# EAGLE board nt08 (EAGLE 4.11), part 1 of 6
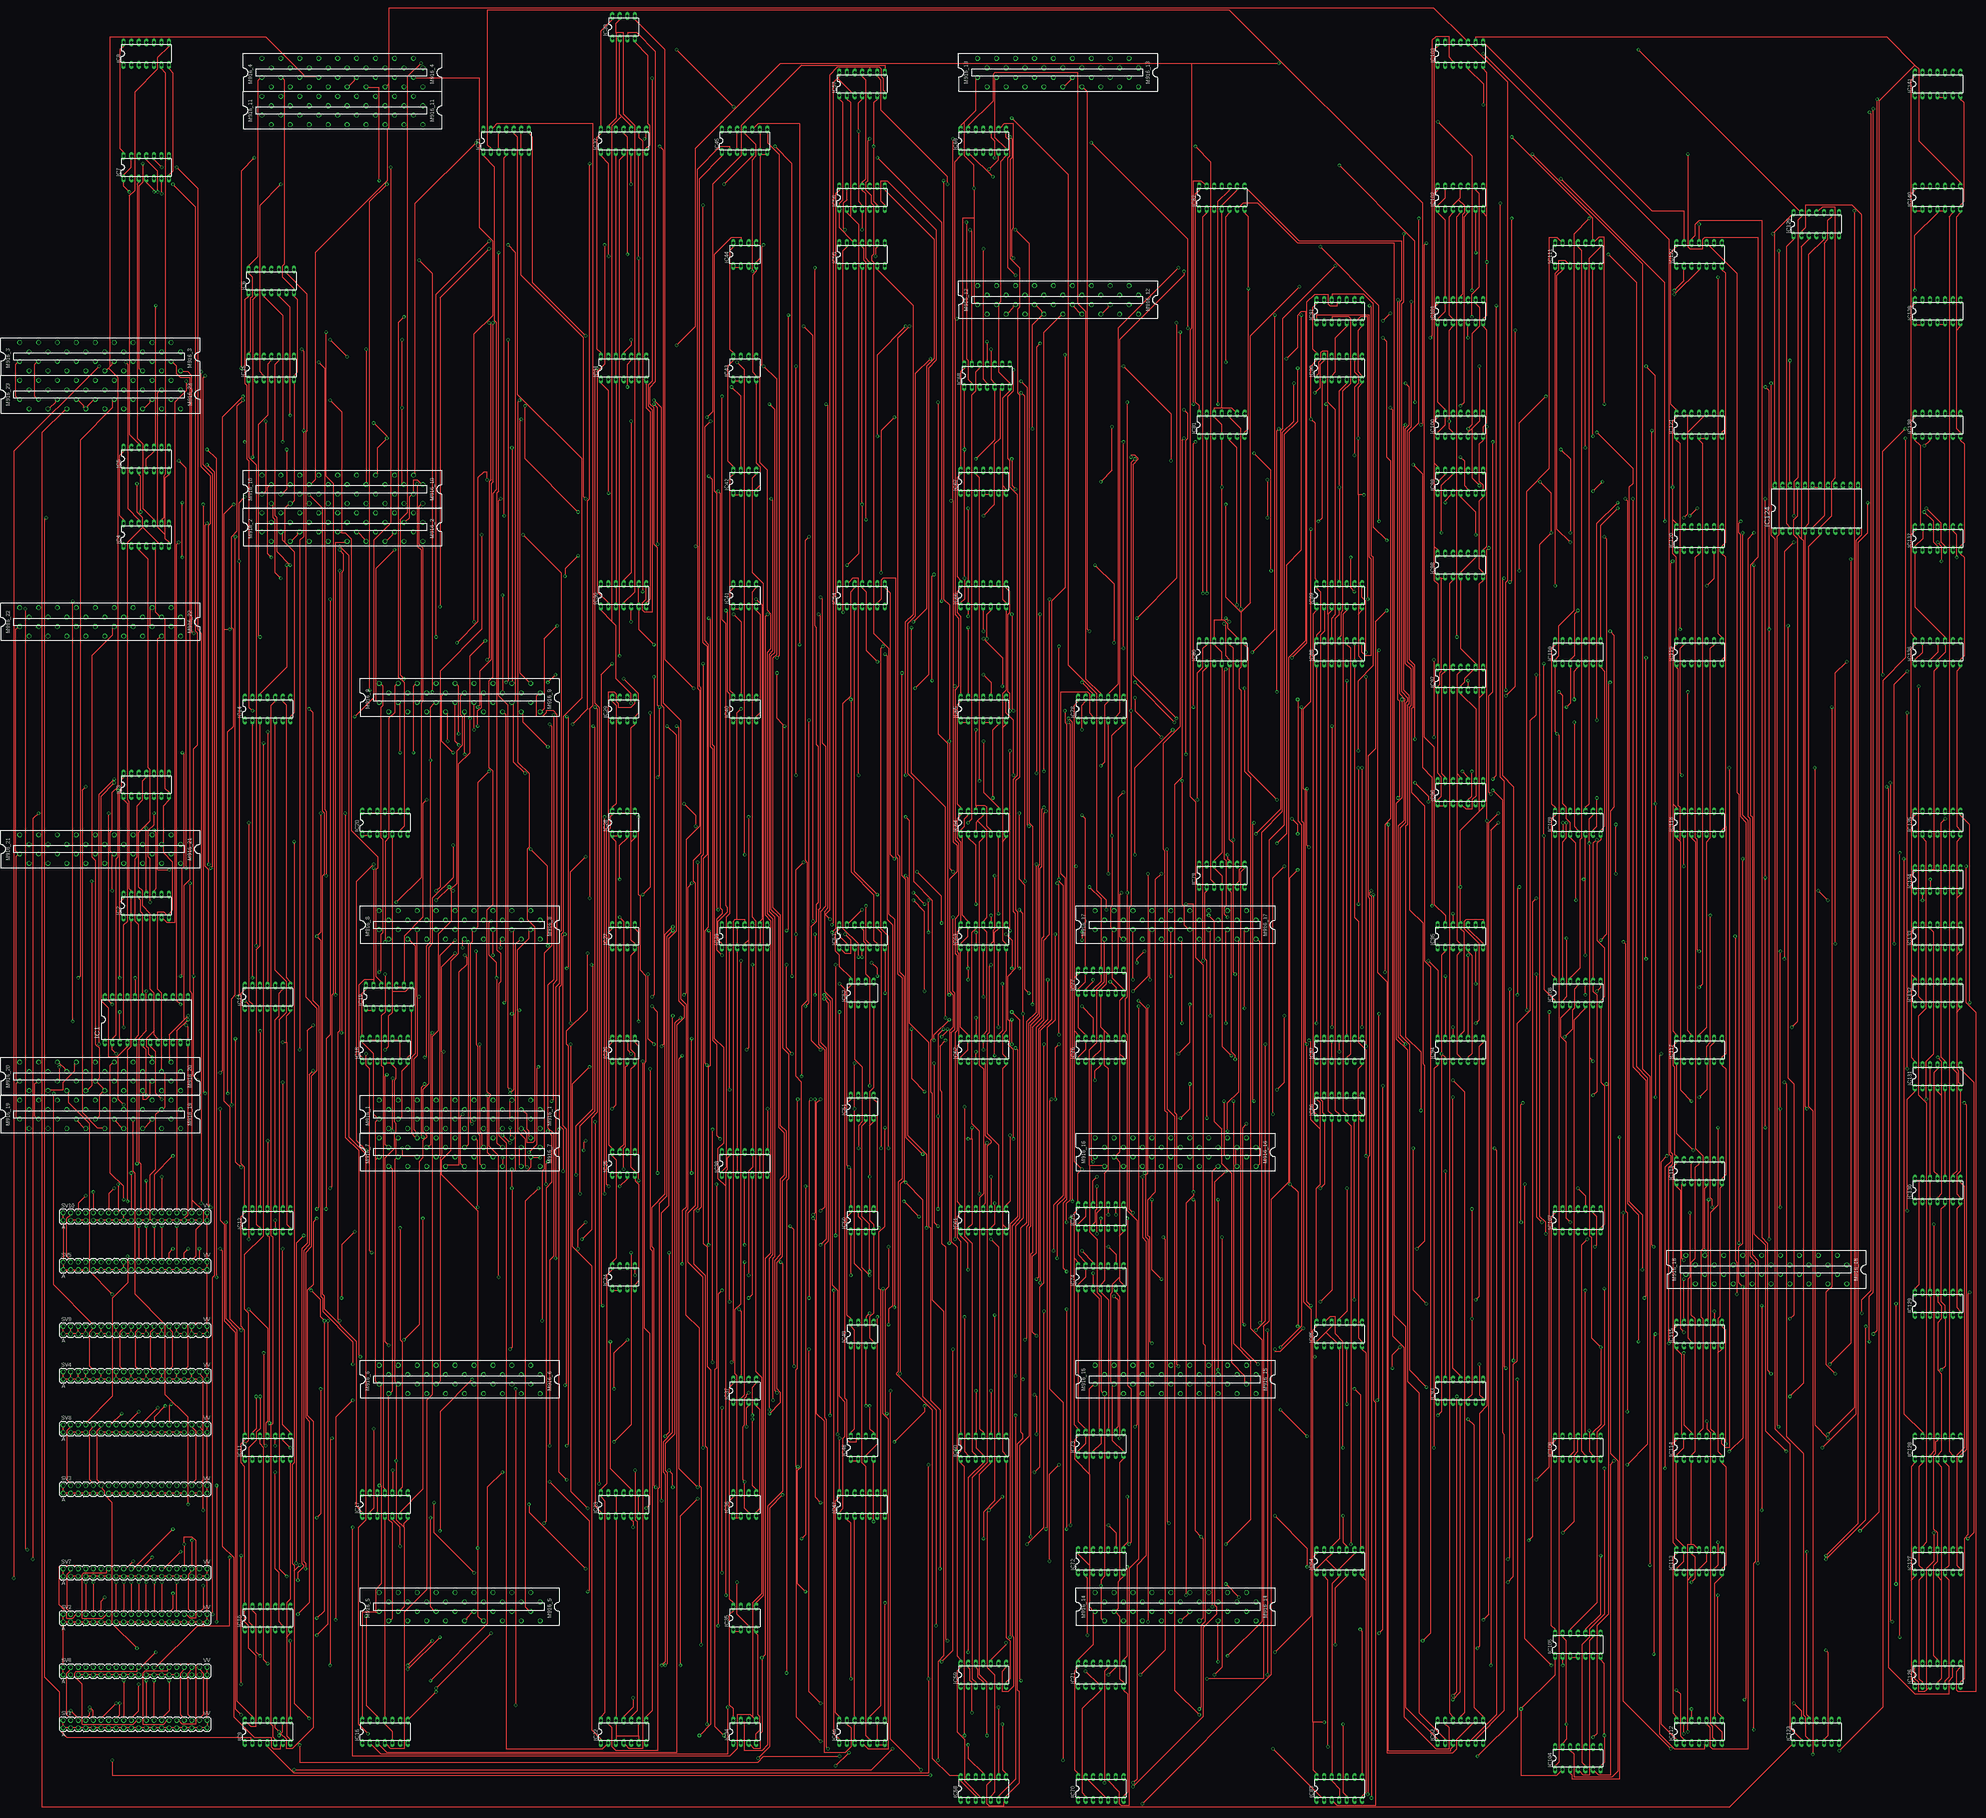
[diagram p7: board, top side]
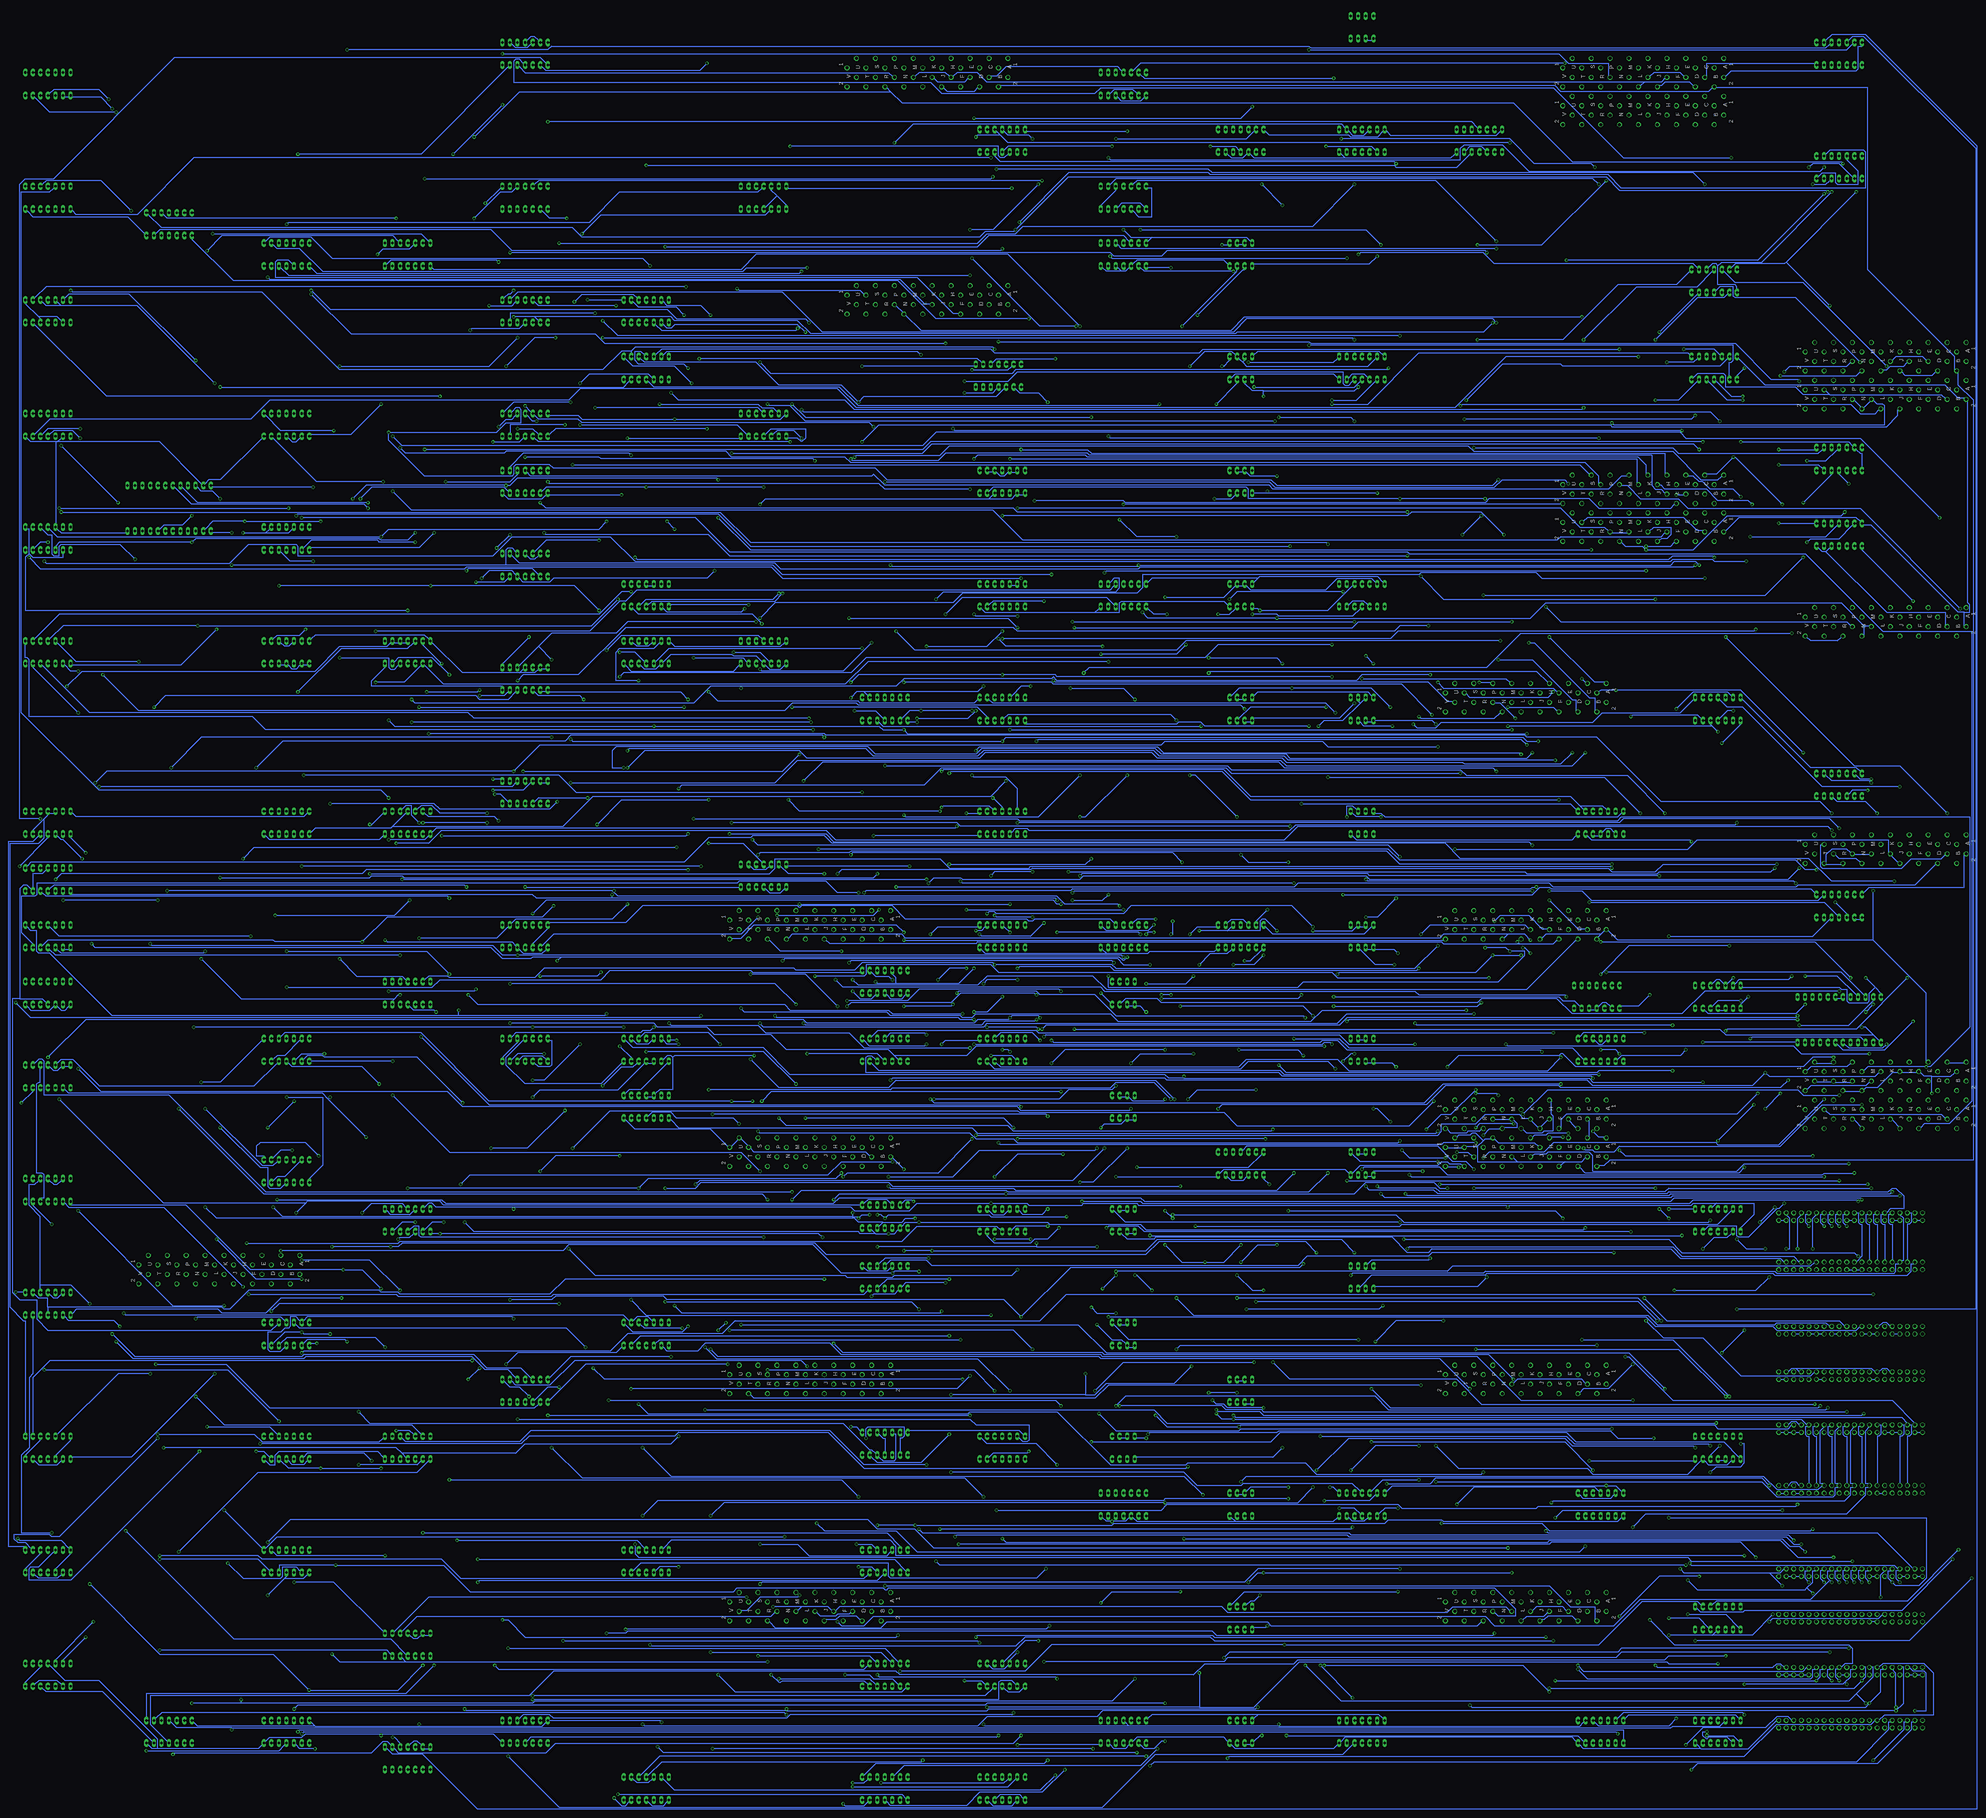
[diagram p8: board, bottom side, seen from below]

No outline drawn. Coordinates in mm, seen from the top.
Copper layers (1*16): Top 0.035mm / dielectric 1.5mm / Bottom 0.035mm
Design rules "10mils": minimum track width 10mil, minimum drill 24mil, track to track 10mil, track to pad 10mil, pad to pad 10mil, via to via 10mil, smd to smd 10mil, copper to edge 40mil, drill to drill 10mil, minimum pad ring 10mil, minimum via ring 8mil, stop-mask expansion 0mil, vias tented up to drill 0mil, thermal gap 10mil

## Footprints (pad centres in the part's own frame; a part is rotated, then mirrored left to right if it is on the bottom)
DIL24-6 = drill 0.813 long: 1 -13.97,-7.62; 2 -11.43,-7.62; 3 -8.89,-7.62; 4 -6.35,-7.62; 5 -3.81,-7.62; 6 -1.27,-7.62; 7 1.27,-7.62; 8 3.81,-7.62; 9 6.35,-7.62; 10 8.89,-7.62; 11 11.43,-7.62; 12 13.97,-7.62; 13 13.97,7.62; 14 11.43,7.62; 15 8.89,7.62; 16 6.35,7.62; 17 3.81,7.62; 18 1.27,7.62; 19 -1.27,7.62; 20 -3.81,7.62; 21 -6.35,7.62; 22 -8.89,7.62; 23 -11.43,7.62; 24 -13.97,7.62
DIL14 = drill 0.813 long: 1 -7.62,-3.81; 2 -5.08,-3.81; 3 -2.54,-3.81; 4 0,-3.81; 5 2.54,-3.81; 6 5.08,-3.81; 7 7.62,-3.81; 8 7.62,3.81; 9 5.08,3.81; 10 2.54,3.81; 11 0,3.81; 12 -2.54,3.81; 13 -5.08,3.81; 14 -7.62,3.81
DIL08 = drill 0.813 long: 1 -3.81,-3.81; 2 -1.27,-3.81; 3 1.27,-3.81; 4 3.81,-3.81; 5 3.81,3.81; 6 1.27,3.81; 7 -1.27,3.81; 8 -3.81,3.81
H807 = drill 1.016 octagon: A1 4.763,28.575; A2 -1.587,28.575; B1 1.587,25.4; B2 -4.763,25.4; C1 4.763,22.225; C2 -1.587,22.225; D1 1.587,19.05; D2 -4.763,19.05; E1 4.763,15.875; E2 -1.587,15.875; F1 1.587,12.7; F2 -4.763,12.7; H1 4.763,9.525; H2 -1.587,9.525; J1 1.587,6.35; J2 -4.763,6.35; K1 4.763,3.175; K2 -1.587,3.175; L1 1.587,0; L2 -4.763,0; M1 4.763,-3.175; M2 -1.587,-3.175; N1 1.587,-6.35; N2 -4.763,-6.35; P1 4.763,-9.525; P2 -1.587,-9.525; R1 1.587,-12.7; R2 -4.763,-12.7; S1 4.763,-15.875; S2 -1.587,-15.875; T1 1.587,-19.05; T2 -4.763,-19.05; U1 4.763,-22.225; U2 -1.587,-22.225; V1 1.587,-25.4; V2 -4.763,-25.4
DEC40PIN = drill 1.016 octagon: A -24.13,-1.27; AA 3.81,-1.27; B -24.13,1.27; BB 3.81,1.27; C -21.59,-1.27; CC 6.35,-1.27; D -21.59,1.27; DD 6.35,1.27; E -19.05,-1.27; EE 8.89,-1.27; F -19.05,1.27; FF 8.89,1.27; H -16.51,-1.27; HH 11.43,-1.27; J -16.51,1.27; JJ 11.43,1.27; K -13.97,-1.27; KK 13.97,-1.27; L -13.97,1.27; LL 13.97,1.27; M -11.43,-1.27; MM 16.51,-1.27; N -11.43,1.27; NN 16.51,1.27; P -8.89,-1.27; PP 19.05,-1.27; R -8.89,1.27; RR 19.05,1.27; S -6.35,-1.27; SS 21.59,-1.27; T -6.35,1.27; TT 21.59,1.27; U -3.81,-1.27; UU 24.13,-1.27; V -3.81,1.27; VV 24.13,1.27; W -1.27,-1.27; X -1.27,1.27; Y 1.27,-1.27; Z 1.27,1.27

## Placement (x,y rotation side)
IC1  74LS154N  [DIL24-6]  0,257.81 0 top
IC2  74LS10N  [DIL14]  0,295.91 0 top
IC3  74LS04N  [DIL14]  0,336.55 0 top
IC4  74LS04N  [DIL14]  0,420.37 0 top
IC5  74LS74N  [DIL14]  0,445.77 0 top
IC6  74LS74N  [DIL14]  41.91,505.46 0 top
IC7  74LS74N  [DIL14]  0,543.56 0 top
IC8  [DIL14]  0,581.66 0 top
IC9  [DIL14]  40.64,19.05 0 top
IC10  [DIL14]  40.64,57.15 0 top
IC11  74LS00N  [DIL14]  40.64,114.3 0 top
IC12  74LS00N  [DIL14]  40.64,190.5 0 top
IC13  74LS00N  [DIL14]  40.64,265.43 0 top
IC14  74LS04N  [DIL14]  40.64,361.95 0 top
IC15  74LS04N  [DIL14]  41.91,476.25 0 top
IC16  74LS00N  [DIL14]  80.01,19.05 0 top
IC17  74LS00N  [DIL14]  80.01,95.25 0 top
IC18  74H40N  [DIL14]  80.01,247.65 0 top
IC19  74H40N  [DIL14]  81.28,265.43 0 top
IC20  74H40N  [DIL14]  80.01,323.85 0 top
IC21  74LS02N  [DIL14]  120.65,552.45 0 top
IC22  74LS02N  [DIL14]  160.02,19.05 0 top
IC23  74LS02N  [DIL14]  160.02,95.25 0 top
IC24  DS75452N  [DIL08]  160.02,171.45 0 top
IC25  DS75452N  [DIL08]  160.02,209.55 0 top
IC26  DS75452N  [DIL08]  160.02,247.65 0 top
IC27  DS75452N  [DIL08]  160.02,285.75 0 top
IC28  DS75452N  [DIL08]  160.02,323.85 0 top
IC29  DS75452N  [DIL08]  160.02,361.95 0 top
IC30  74LS02N  [DIL14]  160.02,400.05 0 top
IC31  74LS02N  [DIL14]  160.02,476.25 0 top
IC32  74LS02N  [DIL14]  160.02,552.45 0 top
IC33  DS75452N  [DIL08]  160.02,590.55 0 top
IC34  DS75452N  [DIL08]  200.66,19.05 0 top
IC35  DS75452N  [DIL08]  200.66,57.15 0 top
IC36  DS75452N  [DIL08]  200.66,95.25 0 top
IC37  DS75452N  [DIL08]  200.66,133.35 0 top
IC38  74LS02N  [DIL14]  200.66,209.55 0 top
IC39  74LS02N  [DIL14]  200.66,285.75 0 top
IC40  DS75452N  [DIL08]  200.66,361.95 0 top
IC41  DS75452N  [DIL08]  200.66,400.05 0 top
IC42  DS75452N  [DIL08]  200.66,438.15 0 top
IC43  DS75452N  [DIL08]  200.66,476.25 0 top
IC44  DS75452N  [DIL08]  200.66,514.35 0 top
IC45  74LS02N  [DIL14]  200.66,552.45 0 top
IC46  74LS02N  [DIL14]  240.03,19.05 0 top
IC47  74LS02N  [DIL14]  240.03,95.25 0 top
IC48  DS75452N  [DIL08]  240.03,114.3 0 top
IC49  DS75452N  [DIL08]  240.03,152.4 0 top
IC50  DS75452N  [DIL08]  240.03,190.5 0 top
IC51  DS75452N  [DIL08]  240.03,228.6 0 top
IC52  DS75452N  [DIL08]  240.03,266.7 0 top
IC53  74LS04N  [DIL14]  240.03,285.75 0 top
IC54  74LS04N  [DIL14]  240.03,400.05 0 top
IC55  74LS04N  [DIL14]  240.03,514.35 0 top
IC56  74LS73N  [DIL14]  240.03,533.4 0 top
IC57  74LS73N  [DIL14]  240.03,571.5 0 top
IC58  74LS73N  [DIL14]  280.67,0 0 top
IC59  74LS00N  [DIL14]  280.67,38.1 0 top
IC60  74LS00N  [DIL14]  280.67,114.3 0 top
IC61  74LS00N  [DIL14]  280.67,190.5 0 top
IC62  74LS74N  [DIL14]  280.67,247.65 0 top
IC63  74LS74N  [DIL14]  280.67,285.75 0 top
IC64  74LS74N  [DIL14]  280.67,323.85 0 top
IC65  74H40N  [DIL14]  280.67,361.95 0 top
IC66  74H40N  [DIL14]  280.67,400.05 0 top
IC67  74H40N  [DIL14]  280.67,438.15 0 top
IC68  74LS10N  [DIL14]  281.94,473.71 0 top
IC69  74LS10N  [DIL14]  280.67,552.45 0 top
IC70  [DIL14]  320.04,0 0 top
IC71  [DIL14]  320.04,38.1 0 top
IC72  [DIL14]  320.04,76.2 0 top
IC73  74LS74N  [DIL14]  320.04,115.57 0 top
IC74  74LS74N  [DIL14]  320.04,171.45 0 top
IC75  74LS74N  [DIL14]  320.04,191.77 0 top
IC76  74LS74N  [DIL14]  320.04,247.65 0 top
IC77  74LS74N  [DIL14]  320.04,270.51 0 top
IC78  74LS00N  [DIL14]  320.04,361.95 0 top
IC79  74LS00N  [DIL14]  360.68,306.07 0 top
IC80  74LS00N  [DIL14]  360.68,381 0 top
IC81  74LS00N  [DIL14]  360.68,457.2 0 top
IC82  74LS00N  [DIL14]  360.68,533.4 0 top
IC83  74LS00N  [DIL14]  400.05,0 0 top
IC84  74LS00N  [DIL14]  400.05,76.2 0 top
IC85  74LS00N  [DIL14]  400.05,152.4 0 top
IC86  74LS30N  [DIL14]  400.05,228.6 0 top
IC87  74LS00N  [DIL14]  400.05,247.65 0 top
IC88  74LS00N  [DIL14]  400.05,381 0 top
IC89  74LS30N  [DIL14]  400.05,400.05 0 top
IC90  74LS00N  [DIL14]  400.05,476.25 0 top
IC91  74LS04N  [DIL14]  400.05,495.3 0 top
IC92  74LS04N  [DIL14]  440.69,19.05 0 top
IC93  74LS04N  [DIL14]  440.69,133.35 0 top
IC94  74LS73N  [DIL14]  440.69,247.65 0 top
IC95  74LS73N  [DIL14]  440.69,285.75 0 top
IC96  74LS51N  [DIL14]  440.69,334.01 0 top
IC97  74LS51N  [DIL14]  440.69,372.11 0 top
IC98  74LS51N  [DIL14]  440.69,410.21 0 top
IC99  74LS04N  [DIL14]  440.69,438.15 0 top
IC100  74LS74N  [DIL14]  440.69,457.2 0 top
IC101  74LS74N  [DIL14]  440.69,495.3 0 top
IC102  74LS74N  [DIL14]  440.69,533.4 0 top
IC103  74LS51N  [DIL14]  440.69,581.66 0 top
IC104  74LS51N  [DIL14]  480.06,10.16 0 top
IC105  74LS51N  [DIL14]  480.06,48.26 0 top
IC106  74LS00N  [DIL14]  480.06,114.3 0 top
IC107  74LS00N  [DIL14]  480.06,190.5 0 top
IC108  74LS10N  [DIL14]  480.06,266.7 0 top
IC109  74LS10N  [DIL14]  480.06,323.85 0 top
IC110  74LS10N  [DIL14]  480.06,381 0 top
IC111  74LS04N  [DIL14]  480.06,514.35 0 top
IC112  74LS04N  [DIL14]  520.7,19.05 0 top
IC113  74LS74N  [DIL14]  520.7,76.2 0 top
IC114  74LS74N  [DIL14]  520.7,114.3 0 top
IC115  74LS74N  [DIL14]  520.7,152.4 0 top
IC116  74LS00N  [DIL14]  520.7,207.01 0 top
IC117  74LS00N  [DIL14]  520.7,247.65 0 top
IC118  74LS00N  [DIL14]  520.7,323.85 0 top
IC119  74H40N  [DIL14]  520.7,381 0 top
IC120  74H40N  [DIL14]  520.7,419.1 0 top
IC121  74H40N  [DIL14]  520.7,457.2 0 top
IC122  74LS04N  [DIL14]  520.7,514.35 0 top
IC123  74LS04N  [DIL14]  560.07,19.05 0 top
IC124  74LS154N  [DIL24-6]  560.07,429.26 0 top
IC125  74LS04N  [DIL14]  560.07,524.51 0 top
IC126  74LS73N  [DIL14]  600.71,38.1 0 top
IC127  74LS73N  [DIL14]  600.71,76.2 0 top
IC128  74LS73N  [DIL14]  600.71,114.3 0 top
IC129  74LS51N  [DIL14]  600.71,162.56 0 top
IC130  74LS51N  [DIL14]  600.71,200.66 0 top
IC131  74LS51N  [DIL14]  600.71,238.76 0 top
IC132  74LS04N  [DIL14]  600.71,266.7 0 top
IC133  74LS30N  [DIL14]  600.71,285.75 0 top
IC134  74LS30N  [DIL14]  600.71,304.8 0 top
IC135  74LS30N  [DIL14]  600.71,323.85 0 top
IC136  74LS74N  [DIL14]  600.71,381 0 top
IC137  74LS74N  [DIL14]  600.71,419.1 0 top
IC138  74LS74N  [DIL14]  600.71,457.2 0 top
IC139  74H40N  [DIL14]  600.71,495.3 0 top
IC140  74H40N  [DIL14]  600.71,533.4 0 top
IC141  74H40N  [DIL14]  600.71,571.5 0 top
M916_1  M302  [H807]  106.68,226.06 90 top
M916_2  M602  [H807]  67.31,422.91 90 top
M916_3  G888  [H807]  -13.97,480.06 90 top
M916_4  M302  [H807]  67.31,575.31 90 top
M916_5  G888  [H807]  106.68,60.96 90 top
M916_6  G888  [H807]  106.68,137.16 90 top
M916_7  M633  [H807]  106.68,213.36 90 top
M916_8  W023  [H807]  106.68,289.56 90 top
M916_9  M916  [H807]  106.68,365.76 90 top
M916_10  M916  [H807]  67.31,435.61 90 top
M916_11  W032  [H807]  67.31,562.61 90 top
M916_12  M602  [H807]  307.34,499.11 90 top
M916_13  G888  [H807]  307.34,575.31 90 top
M916_14  G888  [H807]  346.71,60.96 90 top
M916_15  G879  [H807]  346.71,137.16 90 top
M916_16  M633  [H807]  346.71,213.36 90 top
M916_17  W005  [H807]  346.71,289.56 90 top
M916_18  M228  [H807]  544.83,173.99 90 top
M916_19  M602  [H807]  -13.97,226.06 90 top
M916_20  M307  [H807]  -13.97,238.76 90 top
M916_21  M401  [H807]  -13.97,314.96 90 top
M916_22  M302  [H807]  -13.97,391.16 90 top
M916_23  M602  [H807]  -13.97,467.36 90 top
SV1  [DEC40PIN]  -3.81,21.59 0 top
SV2  [DEC40PIN]  -3.81,57.15 0 top
SV3  [DEC40PIN]  -3.81,100.33 0 top
SV4  [DEC40PIN]  -3.81,138.43 0 top
SV5  [DEC40PIN]  -3.81,175.26 0 top
SV6  [DEC40PIN]  -3.81,39.37 0 top
SV7  [DEC40PIN]  -3.81,72.39 0 top
SV8  [DEC40PIN]  -3.81,120.65 0 top
SV9  [DEC40PIN]  -3.81,153.67 0 top
SV10  [DEC40PIN]  -3.81,191.77 0 top

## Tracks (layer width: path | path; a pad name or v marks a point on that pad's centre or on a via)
00\  (via drill 0.61)
  Top 0.254: v-7.62,255.27 -7.62,289.56 -6.35,290.83 -6.35,330.2 -7.62,331.47 IC3.1 | v361.31,230.5 361.31,212.72 361.95,212.09 M916_16.S2 | v260.99,233.68 256.54,238.12 v256.54,254.63
  Bottom 0.254: -11.43,252.73 -8.89,255.27 v-7.62,255.27 | -11.43,252.73 -13.34,250.82 IC1.1 | v361.31,230.5 358.14,233.68 v260.99,233.68 | v256.54,254.63 40.01,254.63 38.1,252.73 -11.43,252.73
0_TO_AC\  (via drill 0.61)
  Top 0.254: v203.2,508.63 203.2,546.1 204.47,547.37 204.47,551.18 200.66,554.99 IC45.11
  Bottom 0.254: v203.2,508.63 233.04,508.63 234.31,509.9 IC55.2
0_TO_DTB\  (via drill 0.61)
  Top 0.254: IC102.13 435.61,535.94 435.61,533.4 433.07,530.86 IC102.1 433.07,528.32 435.61,525.78 435.61,500.38 IC101.13 435.61,497.84 435.61,495.3 433.07,492.76 IC101.1 433.07,490.22 433.07,464.82 435.61,462.28 IC100.13 435.61,459.74 435.61,457.2 433.07,454.66 IC100.1 | IC62.1 273.05,245.11 275.59,247.65 275.59,250.19 IC62.13 275.59,252.73 273.05,255.27 273.05,280.67 IC63.1 273.05,283.21 275.59,285.75 275.59,288.29 IC63.13 275.59,290.83 273.69,292.74 273.69,319.4 IC64.1 273.05,321.31 274.32,322.58 274.32,325.12 275.59,326.39 IC64.13 | v290.83,339.73 290.83,358.14 288.29,360.68 288.29,364.49 IC65.8 | v379.73,455.93 379.1,455.3 v379.1,367.67
  Bottom 0.254: v290.83,339.73 290.19,339.09 279.4,339.09 275.59,335.28 275.59,328.93 IC64.13 | v379.73,455.93 430.53,455.93 432.44,454.02 IC100.1 | v379.1,367.67 375.92,364.49 328.93,364.49 328.3,363.86 290.19,363.86 288.93,365.12 IC65.8
0_TO_EF
  Top 0.254: IC12.3 38.1,187.96 36.83,189.23 36.83,281.31 38.1,282.57 38.1,356.87 IC14.3
0_TO_EF\  (via drill 0.61)
  Top 0.254: v35.56,361.31 34.29,362.58 34.29,445.13 33.66,445.77 33.66,451.49 | 33.66,451.49 33.66,470.54 33.02,471.17 33.02,499.11 34.29,500.38 IC6.1 | v2.54,535.3 2.54,535.94 0,538.48 IC7.4 | 33.66,451.49 v33.02,451.49
  Bottom 0.254: IC5.1 -7.62,443.23 -7.62,447.68 -6.99,447.68 -5.71,448.94 IC5.13 -4.45,450.21 -3.17,451.49 v33.02,451.49 | v35.56,361.31 37.47,361.31 40.01,358.77 IC14.4 | 40.64,510.54 41.27,511.18 42.55,511.18 43.81,509.9 IC6.10 | 40.64,510.54 40.64,504.19 34.92,504.19 34.29,503.56 34.29,502.92 IC6.1 | v2.54,535.3 26.04,511.81 39.37,511.81 40.64,510.54
0_TO_LPB\
  Top 0.254: IC126.2 595.63,35.56 594.36,36.83 594.36,69.85 595.63,71.12 IC127.2 595.63,73.66 594.36,74.93 594.36,107.95 595.63,109.22 IC128.2 | IC140.6 605.79,528.32 604.52,527.05 604.52,113.03 605.79,111.76 IC128.6
  Bottom 0.254: IC126.2 596.26,34.92 597.53,36.2 603.88,36.2 605.15,34.92 IC126.6 | IC127.2 596.26,71.75 597.53,70.48 603.88,70.48 605.15,71.75 IC127.6 | IC128.2 596.26,109.86 597.53,108.58 603.88,108.58 605.15,109.86 IC128.6
0_TO_STA  (via drill 0.61)
  Top 0.254: v54.61,361.95 55.88,360.68 55.88,264.16 57.78,262.25 57.78,194.94 v57.15,194.31
  Bottom 0.254: v54.61,361.95 48.9,367.67 37.47,367.67 36.2,366.39 IC14.13 | v57.15,194.31 48.9,194.31 IC12.8
0_TO_STA\  (via drill 0.61)
  Top 0.254: IC56.6 245.11,530.86 243.84,532.13 v243.84,550.54 243.84,565.15 245.11,566.42 IC57.6 | v46.99,410.21 46.99,375.92 38.1,367.03 IC14.12 | v234.95,410.21 238.76,414.02 238.76,524.51 236.22,527.05 | 236.22,527.05 234.95,528.32 IC56.2 | 236.22,527.05 236.22,565.15 234.95,566.42 IC57.2 | v434.34,246.38 435.61,245.11 IC94.2 | v434.34,246.38 434.34,279.4 435.61,280.67 IC95.2 | v291.46,125.09 291.46,3.17 285.75,-2.54 IC58.6 | v433.07,125.09 434.34,126.36 v434.34,246.38 | v318.13,410.21 324.49,403.86 v324.49,384.18 | v361.95,375.29 361.31,374.65 361.31,311.79 361.95,311.15 361.95,295.91 361.31,295.27 361.31,293.37 v362.58,292.1
  Bottom 0.254: IC57.2 235.59,568.33 236.85,569.6 243.21,569.6 244.47,568.33 IC57.6 | v243.84,550.54 278.76,550.54 280.04,549.27 IC69.4 | v46.99,410.21 48.26,411.48 55.24,411.48 56.52,410.21 v234.95,410.21 235.59,409.57 317.5,409.57 v318.13,410.21 | IC58.2 276.23,-4.45 277.5,-5.71 283.85,-5.71 285.12,-4.45 IC58.6 | v434.34,246.38 443.23,246.38 445.13,244.47 IC94.6 | v433.07,125.09 v291.46,125.09 | v324.49,384.18 334.01,374.65 361.31,374.65 v361.95,375.29 | v362.58,292.1 368.3,286.38 431.17,286.38 434.98,282.57 IC95.2
01\  (via drill 0.61)
  Top 0.254: v-9.53,334.64 -9.53,312.42 -10.16,311.79 -10.16,252.73 -11.43,251.46 IC1.2 -11.43,248.92 -11.43,247.65 v-10.16,246.38 | v111.76,249.56 111.76,220.34 112.39,219.71 112.39,215.26 M916_7.N1
  Bottom 0.254: v-9.53,334.64 -4.45,334.64 -3.17,333.38 IC3.3 | v111.76,249.56 111.12,248.92 15.24,248.92 12.7,246.38 v-10.16,246.38
1_TO_DF  (via drill 0.61)
  Top 0.254: v482.6,266.06 482.6,269.24 IC108.10 | v552.45,417.83 549.27,414.65 v549.27,278.13 | v45.72,451.49 45.72,494.03 39.37,500.38 IC6.3 | v474.35,448.94 477.52,445.77 v477.52,421
  Bottom 0.254: 484.5,264.8 483.24,266.06 v482.6,266.06 | 484.5,264.8 485.14,264.16 IC108.6 | v549.27,278.13 535.94,264.8 484.5,264.8 | IC137.3 598.17,416.56 596.9,417.83 v552.45,417.83 551.18,419.1 489.58,419.1 488.95,418.46 480.06,418.46 v477.52,421 | v45.72,451.49 304.8,451.49 307.34,448.94 v474.35,448.94
1_TO_DTF  (via drill 0.61)
  Top 0.254: v563.25,78.11 574.04,88.9 574.04,417.83 577.22,421 v577.22,431.17 | v596.26,450.21 598.17,452.12 IC138.3
  Bottom 0.254: v563.25,78.11 530.23,78.11 528.96,76.83 468.63,76.83 462.28,70.48 327.02,70.48 325.75,71.75 IC72.6 | v577.22,431.17 v596.26,450.21
02\  (via drill 0.61)
  Top 0.254: v-8.89,260.35 -8.89,251.46 IC1.3 | v-11.43,262.89 -12.7,264.16 v-12.7,327.02 | v31.75,208.28 29.84,210.19 v29.84,251.46
  Bottom 0.254: v-8.89,260.35 v-11.43,262.89 | v-12.7,327.02 -8.89,330.83 0.64,330.83 1.91,332.11 IC3.5 | v31.75,208.28 33.66,206.38 85.09,206.38 87,208.28 M916_7.D2 | v29.84,251.46 29.21,252.09 -6.99,252.09 -8.26,250.82 IC1.3
03\  (via drill 0.61)
  Top 0.254: -9.53,245.75 -10.16,245.11 -12.7,245.11 -12.7,261.62 -15.24,264.16 -15.24,332.74 v-10.79,337.19 | -9.53,245.75 -6.35,248.92 IC1.4 | v85.72,214.63 85.72,212.09 90.17,212.09 M916_7.E2 | v-7.62,229.24 -9.53,231.14 -9.53,245.75
  Bottom 0.254: v-10.79,337.19 -10.16,337.82 2.54,337.82 4.45,339.73 IC3.9 | v85.72,214.63 85.09,214 82.55,214 81.92,213.36 75.56,213.36 73.66,215.26 19.68,215.26 5.71,229.24 v-7.62,229.24
04\  (via drill 0.61)
  Top 0.254: IC3.11 0,339.09 -1.27,337.82 -1.27,331.47 -3.17,329.56 -3.17,312.42 -3.81,311.79 -3.81,290.83 -2.54,289.56 -2.54,252.73 -3.81,251.46 IC1.5 -3.17,249.56 v-3.17,209.55
  Bottom 0.254: v-3.17,209.55 31.75,209.55 34.29,207.01 82.55,207.01 82.55,212.09 83.82,213.36 97.79,213.36 98.42,212.72 102.23,212.72 102.87,212.09 M916_7.K2
05\  (via drill 0.61)
  Top 0.254: v-10.79,338.45 -15.88,333.38 v-15.88,249.56 | v106.05,226.06 105.41,225.43 105.41,209.55 106.05,208.91 M916_7.L2 | v0,232.41 0,247.65 -1.27,248.92 IC1.6
  Bottom 0.254: v-10.79,338.45 -6.99,338.45 -5.71,339.73 IC3.13 | v-15.88,249.56 -14.61,248.28 -3.17,248.28 -1.91,249.56 IC1.6 | v106.05,226.06 97.79,234.31 13.97,234.31 12.06,232.41 v0,232.41
06\  (via drill 0.61)
  Top 0.254: v-24.77,257.18 v-24.77,398.14 | v119.38,211.46 119.38,208.91 M916_7.R2 | v5.08,231.14 3.17,233.04 3.17,247.01 1.27,248.92 IC1.7
  Bottom 0.254: v-24.77,398.14 -7.62,415.29 IC4.1 | v-24.77,257.18 -15.24,247.65 -1.27,247.65 0.64,249.56 IC1.7 | v119.38,211.46 117.47,213.36 99.06,213.36 95.89,216.53 41.27,216.53 40.64,215.9 20.32,215.9 v5.08,231.14
07\  (via drill 0.61)
  Top 0.254: 2.54,254 2.54,252.73 3.81,251.46 IC1.8 | 2.54,254 2.54,266.7 1.27,267.97 1.27,293.37 -1.27,295.91 -1.27,300.99 -2.54,302.26 -2.54,320.68 1.27,324.49 1.27,341.63 0.64,342.26 0.64,412.12 -2.54,415.29 IC4.3 | v128.27,213.36 130.81,215.9 130.81,241.3 v131.44,241.94 | v1.91,245.11 0.64,246.38 0.64,248.28 0,248.92 0,251.46 2.54,254
  Bottom 0.254: v128.27,213.36 124.46,213.36 123.19,212.09 M916_7.S2 | v131.44,241.94 127.64,245.75 93.98,245.75 93.34,246.38 92.71,246.38 88.27,241.94 12.06,241.94 8.89,245.11 v1.91,245.11
76  (via drill 0.61)
  Top 0.254: v438.15,231.78 438.15,140.97 440.69,138.43 IC93.11 | IC87.12 397.51,250.19 397.51,245.11 IC87.3
  Bottom 0.254: v438.15,231.78 435.61,234.31 409.57,234.31 400.69,243.21 IC87.4 399.42,243.21 398.14,243.21 IC87.3 | IC87.9 404.5,250.82 403.23,249.56 399.42,249.56 398.14,250.82 IC87.12
76+77  (via drill 0.61)
  Top 0.254: 395.61,76.83 397.51,78.74 IC84.12 397.51,81.28 400.05,83.82 400.05,147.32 IC85.4 399.42,149.22 395.61,153.03 | 395.61,76.83 392.43,73.66 IC84.1 | 395.61,76.83 399.42,73.03 IC84.4 | IC84.9 405.13,78.74 400.05,73.66 IC84.4 | IC83.4 400.05,-2.54 400.05,0 397.51,2.54 IC83.12 397.51,5.08 397.51,68.58 400.05,71.12 IC84.4 | 395.61,153.03 397.51,154.94 IC85.12 | 395.61,153.03 392.43,149.86 IC85.1 | v577.85,561.98 578.49,561.34 578.49,167 575.31,163.83 v575.31,159.38
  Bottom 0.254: IC83.1 393.06,-4.45 394.33,-5.71 398.14,-5.71 399.42,-4.45 IC83.4 | IC83.9 404.5,3.17 403.23,1.91 399.42,1.91 398.14,3.17 IC83.12 | IC85.12 398.14,156.84 399.42,158.12 403.23,158.12 404.5,156.84 IC85.9 405.76,156.84 407.67,158.75 574.67,158.75 v575.31,159.38 | v577.85,561.98 600.08,561.98 605.15,567.05 IC141.6
76\  (via drill 0.61)
  Top 0.254: v577.85,149.86 577.85,165.1 579.12,166.37 v579.12,563.25
  Bottom 0.254: v577.85,149.86 572.13,144.15 514.99,144.15 514.35,144.78 458.47,144.78 454.02,140.34 446.4,140.34 443.87,137.79 IC93.10 | v579.12,563.25 582.93,567.05 592.46,567.05 IC141.1 593.73,567.05 595,567.05 IC141.2
76_
  Bottom 0.254: IC87.1 393.06,243.21 401.95,234.31 405.76,234.31 407.04,233.04 IC86.8
77  (via drill 0.61)
  Top 0.254: IC90.1 392.43,473.71 393.06,474.35 393.06,478.15 393.7,478.79 393.7,481.33 394.33,481.96 396.24,481.96 396.24,464.82 398.78,462.28 398.78,393.7 397.51,392.43 397.51,386.08 IC88.12 | v435.61,207.01 435.61,138.43 IC93.13 | v408.94,212.09 408.94,247.65 406.4,250.19 406.4,290.83 405.13,292.1 405.13,375.92 IC88.6 405.13,378.46 405.13,383.54 IC88.9
  Bottom 0.254: IC88.12 398.14,384.18 399.42,382.9 403.23,382.9 404.5,384.18 IC88.9 | v435.61,207.01 430.53,212.09 v408.94,212.09
77\  (via drill 0.61)
  Top 0.254: v579.12,152.4 580.39,153.67 v580.39,566.42 | IC141.5 602.62,567.05 601.35,567.05 IC141.4
  Bottom 0.254: v579.12,152.4 571.5,144.78 515.62,144.78 514.99,145.41 457.83,145.41 453.39,140.97 441.96,140.97 438.79,137.79 IC93.12 | v580.39,566.42 583.57,569.6 598.8,569.6 600.08,568.33 IC141.4
77_  (via drill 0.61)
  Top 0.254: v408.94,381 408.94,398.14 407.67,399.42 407.67,402.59 IC89.8
  Bottom 0.254: v408.94,381 403.86,381 400.69,377.82 IC88.4
+3V@A09U1  (via drill 0.61)
  Top 0.254: IC7.13 -5.08,546.1 -5.08,543.56 -7.62,541.02 IC7.1 -7.62,538.48 -7.62,537.21 v-5.71,535.3 | v320.04,191.13 320.04,189.23 IC75.4 | v322.58,192.41 322.58,194.31 IC75.10 | -1.27,422.91 4.45,417.19 IC4.6 | -1.27,422.91 -1.27,426.08 -3.17,427.99 v-3.17,437.51 | IC5.4 0,443.23 0,445.77 2.54,448.31 IC5.10 3.17,450.21 v3.17,497.2 | -1.27,422.91 -6.35,417.83 -6.35,331.47 -5.71,330.83 -5.71,301.62 -5.08,300.99 IC2.13 -5.08,298.45 -5.08,293.37 IC2.2 -5.08,290.83 -5.08,248.92 -6.35,247.65 v-6.35,196.85 | v259.08,191.77 v254,196.85
  Bottom 0.254: 17.78,511.81 v-5.71,535.3 | 17.78,511.81 18.41,511.18 34.92,511.18 36.2,509.9 IC6.13 | v322.58,192.41 321.31,192.41 v320.04,191.13 318.77,192.41 285.12,192.41 284.48,191.77 v259.08,191.77 | IC2.1 -6.99,291.46 -5.71,291.46 IC2.2 | v-3.17,437.51 0,440.69 IC5.4 | v254,196.85 234.31,196.85 233.68,196.22 50.16,196.22 48.9,197.49 -5.71,197.49 v-6.35,196.85 | v3.17,497.2 17.78,511.81
+3V@B12U1  (via drill 0.61)
  Top 0.254: IC73.10 322.58,120.65 322.58,163.83 320.04,166.37 IC74.4 320.04,168.91 321.31,170.18 321.31,206.38 322.58,207.65 322.58,241.3 321.31,242.57 321.31,254 | IC77.10 321.94,273.69 321.94,269.88 320.04,267.97 IC77.4 320.04,265.43 320.04,255.27 321.31,254 | 321.31,254 322.58,252.73 IC76.10 | IC76.1 312.42,245.11 314.96,247.65 314.96,250.19 IC76.13 314.96,252.73 312.42,255.27 312.42,265.43 IC77.1 312.42,267.97 314.96,270.51 314.96,273.05 IC77.13 314.96,275.59 314.96,325.12 v313.69,326.39 | v254.63,339.73 254.63,391.16 257.18,393.7 257.18,497.2 245.11,509.27 IC55.6
  Bottom 0.254: IC73.4 320.04,113.03 320.04,117.47 320.68,117.47 321.94,118.75 IC73.10 | v254.63,339.73 268.61,325.75 313.06,325.75 v313.69,326.39 | IC77.4 319.4,266.06 318.13,264.8 314.32,264.8 313.06,266.06 IC77.1
+3V@C08U1  (via drill 0.61)
  Top 0.254: v363.86,245.75 360.68,248.92 360.68,300.99 IC79.4 360.68,303.53 360.68,306.07 358.14,308.61 IC79.12 358.14,311.15 360.68,313.69 360.68,375.92 IC80.4 360.68,378.46 360.68,381 358.14,383.54 IC80.12 358.14,386.08 358.14,391.8 360.68,391.8 | IC90.5 402.59,471.17 400.05,468.63 v400.05,436.25 400.05,405.13 IC89.11 | 360.68,391.8 361.31,391.8 362.58,390.52 362.58,389.25 365.76,386.08 IC80.9 | IC82.9 365.76,535.94 360.68,530.86 IC82.4 360.68,528.32 360.68,462.92 | 360.68,462.92 358.14,462.92 358.14,462.28 IC81.12 358.14,459.74 360.68,457.2 360.68,454.66 IC81.4 360.68,452.12 v360.68,436.25 360.68,391.8 | 360.68,462.92 363.86,462.92 365.12,461.64 IC81.9
  Bottom 0.254: 391.16,245.11 391.8,245.75 393.06,245.75 394.33,244.47 IC87.2 | 391.16,245.11 391.16,234.31 395.61,234.31 396.88,233.04 IC86.12 398.14,231.78 399.42,231.78 IC86.11 | IC79.1 353.69,301.62 354.96,300.36 358.77,300.36 360.05,301.62 IC79.4 | IC79.9 365.12,309.25 363.86,307.98 360.05,307.98 358.77,309.25 IC79.12 | 391.16,245.11 390.52,245.75 v363.86,245.75 | IC89.12 398.14,403.23 399.42,403.23 IC89.11 | IC99.2 434.98,434.98 433.7,436.25 v400.05,436.25 v360.68,436.25 | IC88.5 401.95,376.56 400.69,375.29 396.88,375.29 395.61,376.56 IC88.2 394.33,377.82 391.8,380.37 371.48,380.37 370.84,379.73 363.22,379.73 361.31,377.82 IC80.4 360.05,376.56 358.77,375.29 354.96,375.29 353.69,376.56 IC80.1 | 356.24,534.03 358.14,535.94 IC82.12 | 356.24,534.03 353.06,530.86 IC82.1 | 356.24,534.03 360.05,530.23 IC82.4 | IC81.1 352.43,452.75 349.25,452.75 347.98,451.49 346.71,452.75 346.71,455.93 358.14,455.93 360.05,454.02 IC81.4
+3V@C15U1  (via drill 0.61)
  Top 0.254: IC113.1 513.08,73.66 515.62,76.2 515.62,78.74 IC113.13 515.62,81.28 513.08,83.82 513.08,109.22 IC114.1 513.08,111.76 515.62,114.3 515.62,116.84 IC114.13 514.99,118.75 514.99,145.41 513.08,147.32 IC115.1 | IC113.4 520.7,73.66 523.24,76.2 523.24,78.74 IC113.10 | v527.05,64.77 527.05,25.4 528.32,24.13 IC112.8 | v511.81,411.48 511.18,410.85 511.18,213.36 511.81,212.72 511.81,209.55 510.54,208.28 v510.54,149.22
  Bottom 0.254: 521.34,70.48 520.7,71.12 IC113.4 | v527.05,64.77 521.34,70.48 | 521.34,70.48 514.99,70.48 513.72,71.75 IC113.1 | IC114.4 520.07,109.86 518.79,108.58 514.99,108.58 513.72,109.86 IC114.1 | v511.81,411.48 519.43,411.48 522.61,414.65 IC120.5 | v510.54,149.22 512.45,149.22 IC115.1
+3V@D09U1  (via drill 0.61)
  Top 0.254: v594.36,369.57 594.36,265.43 595.63,264.16 IC132.2
  Bottom 0.254: IC110.11 480.69,384.18 481.96,384.18 IC110.10 483.24,384.18 484.5,384.18 IC110.9 485.77,384.18 487.05,382.9 502.92,382.9 511.18,374.65 589.28,374.65 v594.36,369.57
+3V@D10U1  (via drill 0.61)
  Top 0.254: IC138.1 593.09,452.12 595,450.21 595,423.55 IC137.13 595.63,421.64 595.63,419.1 593.09,416.56 IC137.1 593.09,414.02 593.09,396.24 603.25,386.08 IC136.10 603.25,383.54 603.25,381 600.71,378.46 IC136.4 600.71,375.92 599.44,374.65 599.44,307.98 | 599.44,307.98 600.08,307.98 IC134.11 | 599.44,307.98 598.8,307.98 IC134.12 | v-7.62,197.49 -7.62,201.93 -12.06,206.38 -12.06,242.57 -11.43,243.21 M916_20.M1 | v523.88,197.49 523.88,156.84 IC115.10
  Bottom 0.254: IC134.11 601.35,307.98 602.62,306.7 605.79,306.7 605.79,302.26 IC134.6 606.42,301.62 607.7,302.89 608.97,302.89 610.24,301.62 610.24,264.8 | 610.24,264.8 602.62,264.8 601.35,263.52 IC132.4 | 610.24,264.8 612.77,264.8 612.77,166.37 610.24,163.83 604.52,163.83 604.52,157.48 600.71,153.67 525.78,153.67 523.88,155.57 IC115.10 | v-7.62,197.49 -6.99,198.12 55.24,198.12 56.52,196.85 233.04,196.85 234.31,198.12 335.28,198.12 337.19,196.22 467.36,196.22 468.63,197.49 v523.88,197.49
-15V  (via drill 0.61)
  Top 0.254: M916_5.B2 81.92,56.52 82.55,57.15 82.55,88.9 81.28,90.17 81.28,132.08 M916_6.B2 81.92,132.72 82.55,133.35 82.55,207.65 81.92,208.28 M916_7.B2 | M916_14.B2 320.68,56.52 320.04,57.15 v320.04,67.94 320.04,69.85 321.31,71.12 321.31,132.08 M916_15.B2 320.68,132.72 320.04,133.35 320.04,165.1 318.77,166.37 318.77,184.15 316.23,186.69 316.23,208.91 | 316.23,208.91 320.68,208.91 M916_16.B2 | 316.23,208.91 316.23,247.65 318.77,250.19 318.77,267.97 321.31,270.51 321.31,284.48 M916_17.B2
  Bottom 0.254: M916_13.B2 281.31,570.87 95.25,570.87 93.34,568.96 43.81,568.96 42.55,570.23 M916_4.B2 41.27,570.23 -9.53,570.23 -9.53,509.27 -38.73,480.06 -38.73,475.62 M916_3.B2 -40.01,474.98 -40.01,470.54 -45.09,465.45 -45.09,210.82 76.83,210.82 78.74,208.91 80.64,208.91 M916_7.B2 | v320.04,67.94 97.16,67.94 90.17,60.96 81.92,60.96 81.92,56.52 M916_5.B2
ADDR_ACC  (via drill 0.61)
  Top 0.254: v520.7,524.51 520.7,519.43 IC122.11
  Bottom 0.254: v520.7,524.51 520.07,525.14 419.1,525.14 408.94,535.3 362.58,535.3 361.31,536.58 IC82.11
ADDR_ACC\  (via drill 0.61)
  Top 0.254: v534.03,182.88 534.03,333.38 533.4,334.01 533.4,508 523.88,517.52 IC122.10
  Bottom 0.254: v534.03,182.88 483.24,182.88 482.6,183.51 314.32,183.51 309.25,188.59 282.57,188.59 281.31,187.32 IC61.4
B-BRK  (via drill 0.61)
  Top 0.254: IC67.4 281.31,433.7 282.57,433.7 IC67.5 | 367.03,394.33 367.03,375.92 366.39,375.29 366.39,368.94 367.03,368.3 367.03,308.61 366.39,307.98 366.39,304.17 365.76,303.53 IC79.6 | 367.03,394.33 361.95,399.42 v361.95,430.53 | v386.71,503.56 370.2,487.05 370.2,397.51 367.03,394.33
  Bottom 0.254: IC67.1 273.69,433.7 274.95,433.7 IC67.2 276.23,433.7 277.5,432.44 285.12,432.44 | v361.95,430.53 360.05,432.44 285.12,432.44 | 285.12,432.44 283.85,433.7 IC67.5 | v386.71,503.56 601.35,503.56 605.15,499.75 IC139.9
B-BRK\  (via drill 0.61)
  Top 0.254: 157.48,17.78 157.48,21.59 IC22.12 157.48,24.13 157.48,90.17 IC23.3 157.48,92.71 157.48,97.79 IC23.12 | 157.48,17.78 157.48,16.51 IC22.3 | 165.1,17.78 165.1,21.59 IC22.9 | 165.1,17.78 165.1,16.51 IC22.6 | 157.48,17.78 165.1,17.78 | IC23.6 165.1,92.71 165.1,97.79 IC23.9 | IC21.3 118.11,549.91 118.11,554.99 IC21.12 | v147.32,432.44 146.69,433.07 146.69,486.41 125.73,507.37 125.73,547.37 IC21.6 125.73,549.91 125.73,554.99 IC21.9 | v140.97,103.5 138.43,106.05 v138.43,220.98 | v121.92,234.31 121.28,234.95 121.28,363.22 118.11,366.39 118.11,431.8 v118.75,432.44
  Bottom 0.254: IC23.3 158.12,90.81 159.38,89.53 163.19,89.53 164.47,90.81 IC23.6 | IC67.6 285.12,434.98 283.85,436.25 198.75,436.25 198.12,435.61 198.12,432.44 v147.32,432.44 v118.75,432.44 | IC21.3 118.75,549.27 120.02,550.54 123.83,550.54 125.09,549.27 IC21.6 | v140.97,103.5 153.03,103.5 156.84,99.69 IC23.12 | v138.43,220.98 133.35,226.06 130.18,226.06 v121.92,234.31
B-RUN  (via drill 0.61)
  Top 0.254: v351.79,550.54 356.87,545.47 356.87,304.8 358.14,303.53 IC79.3
  Bottom 0.254: v351.79,550.54 281.94,550.54 281.94,547.37 281.31,546.74 280.04,546.74 278.76,548 IC69.3
B-XSTA  (via drill 0.61)
  Top 0.254: v43.18,114.94 43.18,116.84 IC11.10 | v173.99,118.11 175.26,119.38 v175.26,179.71 | v485.77,181.61 486.41,182.25 486.41,191.77 485.14,193.04 IC107.9 | v504.82,455.3 504.82,182.25 v505.46,181.61
  Bottom 0.254: v43.18,114.94 43.81,115.57 88.9,115.57 91.44,118.11 v173.99,118.11 | v175.26,179.71 179.07,183.51 227.97,183.51 232.41,179.07 339.73,179.07 343.54,182.88 481.96,182.88 483.24,181.61 v485.77,181.61 v505.46,181.61 | v504.82,455.3 522.61,455.3 527.68,460.38 IC121.8
BAC_00  (via drill 0.61)
  Top 0.254: v232.41,286.38 232.41,285.75 234.95,283.21 IC53.2 | v229.87,287.02 231.14,288.29 231.14,534.67 232.41,535.94 IC56.14
  Bottom 0.254: v232.41,286.38 231.78,287.02 v229.87,287.02 | IC56.3 236.85,528.96 234.95,527.05 230.5,527.05 230.5,536.58 231.78,536.58 IC56.14
BAC_00\  (via drill 0.61)
  Top 0.254: v234.31,286.38 236.22,284.48 236.22,280.04 234.31,280.04 233.04,281.31 IC53.1 | v262.25,287.02 v262.25,297.81 | v411.48,299.72 411.48,130.18 412.12,129.54 412.12,-5.71 399.42,-5.71 398.14,-4.45 IC83.3
  Bottom 0.254: v234.31,286.38 234.95,287.02 v262.25,287.02 | v262.25,297.81 262.89,298.45 411.48,298.45 | 411.48,298.45 436.88,298.45 438.15,299.72 593.09,299.72 IC134.1 | 411.48,298.45 v411.48,299.72
BAC_01  (via drill 0.61)
  Top 0.254: v236.22,365.12 236.22,307.34 243.84,299.72 243.84,284.48 245.11,283.21 IC53.6 | v257.81,368.94 262.25,373.38 262.25,476.25 264.8,478.79 264.8,522.61 248.28,539.12 246.38,539.12 246.38,532.13 247.65,530.86 IC56.7
  Bottom 0.254: v236.22,365.12 240.03,368.94 v257.81,368.94 | IC56.10 242.57,535.94 247.65,530.86 IC56.7
BAC_01\  (via drill 0.61)
  Top 0.254: v241.3,295.91 241.3,284.48 242.57,283.21 IC53.5 | v560.71,300.99 v563.88,297.81 | v595.63,297.81 595.63,299.72 IC134.2 | v410.85,-3.17 410.85,299.08 410.21,299.72 410.21,300.36 v410.85,300.99
  Bottom 0.254: v241.3,295.91 241.94,296.55 259.71,296.55 262.25,299.08 409.57,299.08 411.48,300.99 | 411.48,300.99 v560.71,300.99 | v563.88,297.81 v595.63,297.81 | v410.85,-3.17 408.31,-5.71 407.04,-5.71 405.76,-4.45 IC83.6 | 411.48,300.99 v410.85,300.99
BAC_02  (via drill 0.61)
  Top 0.254: v229.87,289.56 230.5,290.19 230.5,572.13 231.78,573.4 | 231.78,573.4 232.41,574.04 IC57.14 | 231.78,573.4 236.85,568.33 IC57.3
  Bottom 0.254: v229.87,289.56 231.78,287.65 245.75,287.65 247.01,288.93 IC53.8
BAC_02\  (via drill 0.61)
  Top 0.254: v246.38,214.63 246.38,287.02 245.11,288.29 IC53.9 | v386.08,154.94 386.08,200.03 v383.54,202.56 383.54,305.44 v386.08,307.98 | v598.17,304.8 598.17,302.26 IC134.3
  Bottom 0.254: v246.38,214.63 257.18,203.84 382.27,203.84 v383.54,202.56 | v386.08,154.94 387.99,153.03 404.5,153.03 407.04,155.57 IC85.8 | v598.17,304.8 596.26,306.7 495.3,306.7 494.03,307.98 v386.08,307.98
BAC_03  (via drill 0.61)
  Top 0.254: v229.24,291.46 227.97,292.74 227.97,293.37 229.24,294.64 229.24,574.67 231.78,577.22 242.57,577.22 | 242.57,577.22 242.57,576.58 IC57.10 | 242.57,577.22 245.75,577.22 246.38,576.58 246.38,574.04 247.01,573.4 247.01,569.6 247.65,568.96 IC57.7
  Bottom 0.254: v229.24,291.46 235.59,291.46 236.85,290.19 IC53.12
BAC_03\  (via drill 0.61)
  Top 0.254: v240.03,294.64 235.59,290.19 IC53.13 | v292.74,294.64 294,293.37 v294,259.71 294,191.13 291.46,188.59 v291.46,138.43 | v405.13,133.99 407.04,132.08 407.04,80.64 IC84.8 | v460.38,302.26 459.74,301.62 v459.74,266.06
  Bottom 0.254: v292.74,294.64 v240.03,294.64 | v291.46,138.43 295.91,133.99 v405.13,133.99 | v460.38,302.26 461.01,302.89 598.8,302.89 600.08,301.62 IC134.4 | v459.74,266.06 456.56,262.89 353.69,262.89 351.79,260.99 318.77,260.99 317.5,259.71 v294,259.71
BAC_04
  Top 0.254: IC95.7 448.31,283.21 443.23,288.29 IC95.10
BAC_04\  (via drill 0.61)
  Top 0.254: v463.55,83.19 464.82,84.45 464.82,297.18 v466.09,298.45
  Bottom 0.254: v463.55,83.19 403.23,83.19 400.69,80.64 IC84.11 | v466.09,298.45 466.73,299.08 601.35,299.08 602.62,300.36 IC134.5
BAC_05
  Top 0.254: IC58.3 278.13,-2.54 273.05,2.54 IC58.14 272.42,4.45 269.24,4.45 263.52,10.16 263.52,127 251.46,139.06 252.09,139.7 252.09,203.2 253.37,204.47 253.37,271.78 252.09,273.05 252.09,311.79 251.46,312.42 251.46,405.76 247.01,405.76 246.38,405.13 246.38,398.78 245.11,397.51 IC54.6
BAC_05\  (via drill 0.61)
  Top 0.254: v294.64,150.5 295.27,151.13 295.27,188.59 295.91,189.23 295.91,256.54 299.08,259.71 299.08,309.25 299.72,309.88 v299.72,393.7
  Bottom 0.254: v294.64,150.5 395.61,150.5 396.88,149.22 IC85.3 | v299.72,393.7 294,399.42 245.75,399.42 243.21,396.88 IC54.5
BAC_06  (via drill 0.61)
  Top 0.254: IC58.10 283.21,2.54 281.94,1.27 281.94,-5.08 282.57,-5.71 287.65,-5.71 287.65,-4.45 IC58.7 288.29,-2.54 292.74,1.91 292.74,32.38 292.1,33.02 292.1,115.57 294,117.47 294,118.75 293.37,119.38 293.37,137.16 | v250.82,311.79 249.56,313.06 249.56,400.69 247.65,402.59 IC54.8 | v298.45,309.88 298.45,260.35 295.27,257.18 295.27,189.87 293.37,187.96 293.37,137.16 | v420.37,147.96 417.83,145.41 v417.83,140.97 | 293.37,137.16 v294,137.16
  Bottom 0.254: v250.82,311.79 252.73,309.88 v298.45,309.88 | v420.37,147.96 426.72,154.31 516.25,154.31 517.52,155.57 IC115.12 | v417.83,140.97 414.02,137.16 v294,137.16
BAC_06\  (via drill 0.61)
  Top 0.254: v298.45,151.76 297.18,153.03 297.18,178.44 298.45,179.71 298.45,255.27 300.99,257.81 300.99,284.48 302.89,286.38 v302.89,398.78
  Bottom 0.254: v298.45,151.76 401.95,151.76 404.5,149.22 IC85.6 | v302.89,398.78 300.36,401.32 242.57,401.32 241.3,402.59 241.3,405.76 243.21,405.76 244.47,404.5 IC54.9
BAC_07  (via drill 0.61)
  Top 0.254: v238.76,278.76 238.76,283.21 233.68,288.29 233.68,363.86 236.22,366.39 236.22,401.32 237.49,402.59 IC54.12 | v429.89,277.5 433.07,274.32 433.07,252.73 IC94.14 | v590.55,374.65 586.11,370.2 v586.11,283.21
  Bottom 0.254: v238.76,278.76 240.03,277.5 241.3,278.76 428.62,278.76 | 428.62,278.76 v429.89,277.5 | IC94.3 437.51,243.21 436.25,241.94 432.44,241.94 431.8,242.57 431.8,250.82 432.44,250.82 IC94.14 | v590.55,374.65 593.09,374.65 595,376.56 IC136.2 | v586.11,283.21 584.84,281.94 452.12,281.94 448.31,278.13 438.79,278.13 438.15,278.76 428.62,278.76
BAC_07\  (via drill 0.61)
  Top 0.254: v238.76,339.73 238.76,405.76 236.85,405.76 235.59,404.5 IC54.13 | v254.63,325.75 255.91,324.49 255.91,256.54 262.25,250.19 262.25,188.59 262.89,187.96 262.89,130.18 266.06,127 v266.06,73.66
  Bottom 0.254: v238.76,339.73 252.73,325.75 v254.63,325.75 | v266.06,73.66 269.24,70.48 318.13,70.48 318.77,71.12 318.77,75.56 401.95,75.56 404.5,73.03 IC84.6
BAC_08  (via drill 0.61)
  Top 0.254: v240.03,278.76 240.03,280.67 IC53.4 | v443.23,279.4 443.23,252.73 IC94.10 | v570.23,377.82 566.42,374.01 v566.42,283.21
  Bottom 0.254: v240.03,278.76 240.66,279.4 v443.23,279.4 448.31,279.4 451.49,282.57 565.78,282.57 v566.42,283.21 | IC94.7 448.31,245.11 443.23,250.19 IC94.10 | v570.23,377.82 591.18,377.82 597.53,384.18 IC136.12
BAC_08\  (via drill 0.61)
  Top 0.254: v238.76,214.63 238.76,222.25 240.03,223.52 240.03,241.94 237.49,244.47 237.49,280.67 IC53.3 | v254.63,203.2 260.35,197.49 260.35,131.44 264.8,127 v264.8,54.61 | v407.04,53.34 407.67,52.7 407.67,5.08 IC83.8
  Bottom 0.254: v238.76,214.63 250.19,203.2 v254.63,203.2 | v264.8,54.61 266.06,53.34 v407.04,53.34
BAC_09
  Bottom 0.254: IC53.10 243.21,290.19 244.47,291.46 269.88,291.46 270.51,290.83 271.78,290.83 272.42,291.46 313.06,291.46 317.5,295.91 347.98,295.91 348.62,295.27 349.25,295.91 401.32,295.91 407.04,290.19 432.44,290.19 IC95.14 433.07,288.29 438.15,283.21 IC95.3
BAC_09\  (via drill 0.61)
  Top 0.254: v242.57,235.59 242.57,271.78 241.3,273.05 241.3,283.21 240.66,283.85 240.66,287.65 240.03,288.29 IC53.11 | v303.53,231.14 302.89,230.5 302.89,133.99 307.34,129.54 v307.34,9.53
  Bottom 0.254: v242.57,235.59 243.84,234.31 258.44,234.31 261.62,231.14 v303.53,231.14 | v307.34,9.53 307.98,8.89 394.97,8.89 399.42,4.45 IC83.11
BAC_10\  (via drill 0.61)
  Top 0.254: v48.26,114.3 45.72,116.84 IC11.9 | v175.26,106.68 176.53,105.41 v176.53,100.97 | v378.46,91.44 389.25,80.64 v389.25,74.3 | v225.43,393.7 226.06,393.06 226.06,295.27 225.43,294.64 225.43,249.56 227.33,247.65 227.33,194.94 v226.06,193.68 | v223.52,191.13 224.16,190.5 224.16,97.79 v226.06,95.89
  Bottom 0.254: v48.26,114.3 48.9,114.94 89.53,114.94 92.08,117.47 164.47,117.47 v175.26,106.68 | v176.53,100.97 181.61,95.89 v226.06,95.89 374.01,95.89 v378.46,91.44 | v389.25,74.3 395.61,74.3 396.88,73.03 IC84.3 | v225.43,393.7 229.87,393.7 231.78,395.61 IC54.1 | v226.06,193.68 v223.52,191.13
BAC_11\  (via drill 0.61)
  Top 0.254: v402.59,201.29 402.59,160.02 400.05,157.48 IC85.11 | v480.06,201.29 482.6,198.75 482.6,195.58 IC107.10 | v245.11,299.72 237.49,307.34 237.49,394.97 IC54.3 | v257.18,297.81 260.99,294 v260.99,267.33 | v332.74,264.16 335.28,261.62 335.28,207.01 v334.64,206.38
  Bottom 0.254: v480.06,201.29 v402.59,201.29 399.42,204.47 336.55,204.47 v334.64,206.38 | v245.11,299.72 247.01,297.81 v257.18,297.81 | v260.99,267.33 261.62,267.97 308.61,267.97 312.42,264.16 v332.74,264.16
BLK_IN_SYNC  (via drill 0.61)
  Top 0.254: v496.57,108.58 503.56,115.57 503.56,238.12 499.75,241.94 499.75,504.82 v490.22,514.35
  Bottom 0.254: v496.57,108.58 476.88,108.58 475.62,109.86 IC106.2 | v490.22,514.35 488.31,516.25 479.43,516.25 478.15,517.52 IC111.12
BLK_IN_SYNC\  (via drill 0.61)
  Top 0.254: v250.82,116.2 260.99,126.36 v260.99,128.27 | v412.75,130.18 413.38,130.81 v413.38,259.71 | v462.92,260.99 462.92,434.98 470.54,442.6 470.54,520.07 473.07,520.07 474.35,518.79 IC111.13
  Bottom 0.254: v250.82,116.2 190.5,116.2 187.32,119.38 91.44,119.38 88.27,116.2 38.73,116.2 33.66,111.12 IC11.1 | v260.99,128.27 262.89,130.18 v412.75,130.18 | v413.38,259.71 414.02,259.08 462.92,259.08 | 462.92,259.08 579.12,259.08 600.08,280.04 603.88,280.04 604.52,280.67 604.52,287.65 606.42,287.65 607.7,288.93 IC133.8 | 462.92,259.08 v462.92,260.99
BMB_00  (via drill 0.61)
  Top 0.254: v419.74,332.11 420.37,332.74 420.37,364.49 419.74,365.12 v419.74,499.11
  Bottom 0.254: v419.74,332.11 436.25,332.11 437.51,330.83 IC96.3 | v419.74,499.11 408.31,499.11 IC91.8
BMB_00\  (via drill 0.61)
  Top 0.254: v379.1,316.87 382.27,320.04 382.27,410.21 387.35,415.29 v387.35,494.03
  Bottom 0.254: v379.1,316.87 367.67,316.87 361.31,310.51 IC79.11 | v387.35,494.03 389.89,496.57 402.59,496.57 404.5,498.48 IC91.9
BMB_01  (via drill 0.61)
  Top 0.254: v415.93,418.46 411.48,422.91 411.48,497.84 408.31,501.01 397.51,501.01 397.51,500.38 IC91.12
  Bottom 0.254: v415.93,418.46 433.7,418.46 437.51,414.65 IC98.12
BMB_01\  (via drill 0.61)
  Top 0.254: v370.84,381 378.46,388.62 v378.46,494.03
  Bottom 0.254: v370.84,381 361.95,381 358.77,377.82 IC80.3 | v378.46,494.03 381.63,497.2 393.06,497.2 394.33,498.48 IC91.13
BMB_02  (via drill 0.61)
  Top 0.254: v421,365.12 421,332.11 419.1,330.2 419.1,251.46 422.91,247.65 422.91,136.53 426.72,132.72 426.72,25.4 435.61,16.51 IC92.2
  Bottom 0.254: v421,365.12 422.27,366.39 436.25,366.39 437.51,367.67 IC97.3
BMB_02\
  Top 0.254: IC82.6 366.39,530.23 367.67,531.5 372.75,531.5 386.08,518.16 418.46,518.16 418.46,158.75 422.27,154.94 422.27,27.3 433.07,16.51 IC92.1
BMB_03  (via drill 0.61)
  Top 0.254: v451.49,334.64 454.66,331.47 454.66,119.38 455.3,118.75 455.3,26.04 445.77,16.51 IC92.6
  Bottom 0.254: v451.49,334.64 441.32,334.64 438.79,337.19 IC96.12
BMB_03\  (via drill 0.61)
  Top 0.254: v422.27,457.2 421.64,456.56 421.64,368.3 423.55,366.39 423.55,363.86 422.91,363.22 422.91,323.21 422.27,322.58 422.27,252.09 427.36,247.01 v427.36,227.33 | v452.12,214.63 452.75,214 452.75,24.77 443.87,15.88 IC92.5
  Bottom 0.254: v422.27,457.2 369.57,457.2 366.39,454.02 IC81.6 | v427.36,227.33 440.06,214.63 v452.12,214.63
BMB_05
  Top 0.254: IC92.12 438.15,24.13 436.88,25.4 436.88,403.86 438.15,405.13 IC98.3
BMB_05\  (via drill 0.61)
  Top 0.254: v417.19,462.92 417.83,462.28 417.83,151.76 421.64,147.96 421.64,24.13 432.44,13.34 436.88,13.34 436.88,20.32 435.61,21.59 IC92.13
  Bottom 0.254: v417.19,462.92 362.58,462.92 361.31,461.64 IC81.11
BMB_06  (via drill 0.61)
  Top 0.254: v438.15,29.84 440.69,32.38 440.69,128.27 IC93.4
  Bottom 0.254: v438.15,29.84 281.94,29.84 281.94,35.56 281.31,36.2 277.5,36.2 276.23,34.92 IC59.2
BMB_06\  (via drill 0.61)
  Top 0.254: v429.26,134.62 423.55,140.34 423.55,249.56 420.37,252.73 420.37,321.94 422.27,323.85 422.27,363.86 422.91,364.49 422.91,365.76 421,367.67 421,497.84 421.64,498.48 v421.64,521.34
  Bottom 0.254: v429.26,134.62 433.07,134.62 437.51,130.18 IC93.3 | v421.64,521.34 415.29,527.68 360.05,527.68 358.77,528.96 IC82.3
BMB_07  (via drill 0.61)
  Top 0.254: v438.15,31.11 439.42,32.38 v439.42,131.44
  Bottom 0.254: v438.15,31.11 286.38,31.11 283.85,33.66 IC59.5 | v439.42,131.44 442.6,134.62 445.77,134.62 447.68,136.53 IC93.8
BMB_07\  (via drill 0.61)
  Top 0.254: v347.98,452.75 347.35,452.12 347.35,339.09 344.81,336.55 344.81,226.69 345.44,226.06 345.44,142.24 v346.07,141.6
  Bottom 0.254: v347.98,452.75 350.52,455.3 356.24,455.3 357.5,454.02 IC81.3 | v346.07,141.6 347.98,143.51 424.18,143.51 432.44,135.25 443.87,135.25 445.13,136.53 IC93.9
BMB_08  (via drill 0.61)
  Top 0.254: v288.29,48.9 288.29,48.26 283.21,43.18 IC59.10 | v427.99,49.53 430.53,52.07 430.53,275.59 428.62,277.5 428.62,329.56 424.18,334.01 424.18,361.95 424.81,362.58 424.81,375.92 422.91,377.82 422.91,455.3 424.18,456.56 v424.18,498.48
  Bottom 0.254: v288.29,48.9 288.93,49.53 v427.99,49.53 | v424.18,498.48 421.64,501.01 404.5,501.01 403.23,499.75 IC91.10
BMB_08\  (via drill 0.61)
  Top 0.254: v384.18,379.1 389.25,384.18 389.25,498.48 391.8,501.01 396.24,501.01 396.24,497.84 396.88,497.2 399.42,497.2 399.42,498.48 IC91.11
  Bottom 0.254: v384.18,379.1 367.67,379.1 366.39,377.82 IC80.6
BMB_09  (via drill 0.61)
  Top 0.254: v281.94,17.78 281.94,35.56 279.4,38.1 279.4,105.41 283.21,109.22 IC60.5
  Bottom 0.254: v281.94,17.78 282.57,17.14 438.79,17.14 440.06,15.88 IC92.4
BMB_09\  (via drill 0.61)
  Top 0.254: v416.56,323.21 416.56,12.7 437.51,12.7 437.51,13.34 438.15,13.97 IC92.3 | v379.1,331.47 369.57,341 369.57,382.27 368.3,383.54 IC80.8
  Bottom 0.254: v416.56,323.21 408.31,331.47 v379.1,331.47
BMB_10  (via drill 0.61)
  Top 0.254: v443.23,123.83 445.13,121.92 445.13,27.3 448.31,24.13 IC92.8
  Bottom 0.254: v443.23,123.83 291.46,123.83 289.56,121.92 271.78,121.92 271.78,116.84 272.42,116.2 273.69,116.2 274.95,117.47 IC60.13
BMB_10\  (via drill 0.61)
  Top 0.254: v413.38,381.63 412.75,381 412.75,273.69 415.93,270.51 415.93,12.06 438.15,12.06 439.42,13.34 439.42,16.51 445.13,22.23 IC92.9
  Bottom 0.254: v413.38,381.63 408.31,386.71 362.58,386.71 361.31,385.44 IC80.11
BMB_11  (via drill 0.61)
  Top 0.254: v276.86,25.4 276.86,35.56 276.23,36.2 276.23,40.01 275.59,40.64 IC59.13
  Bottom 0.254: v276.86,25.4 277.5,24.77 351.79,24.77 353.06,23.5 431.17,23.5 432.44,24.77 441.32,24.77 442.6,23.5 IC92.10
BMB_11\  (via drill 0.61)
  Top 0.254: v422.27,249.56 419.74,252.09 419.74,322.58 421.64,324.49 421.64,364.49 422.27,365.12 420.37,367.03 420.37,498.48 421,499.11 421,518.79 386.71,518.79 368.94,536.58 IC82.8 | v438.15,237.49 441.96,233.68 441.96,25.4 440.69,24.13 IC92.11
  Bottom 0.254: v422.27,249.56 434.34,237.49 v438.15,237.49
BMB_TO_DTB  (via drill 0.61)
  Top 0.254: IC59.12 278.13,40.64 278.76,40.01 278.76,37.47 280.67,35.56 IC59.4 | v275.59,45.72 275.59,104.14 280.67,109.22 IC60.4 280.67,111.76 278.13,114.3 278.13,116.84 IC60.12 278.13,119.38 v278.13,133.35 | IC96.2 434.98,329.56 433.7,329.56 IC96.1 433.07,331.47 434.34,332.74 434.34,339.09 433.07,340.36 433.07,367.03 IC97.1 433.07,369.57 433.7,370.2 433.7,374.01 434.34,374.65 434.34,405.76 | 434.34,405.76 434.98,405.76 IC98.2 | 434.34,405.76 433.7,405.76 IC98.1 | v469.26,466.73 460.38,457.83 v460.38,408.31 | v380.37,147.96 387.35,154.94 387.35,323.21 386.08,324.49 v386.08,365.12
  Bottom 0.254: IC59.1 273.69,33.66 274.95,32.38 278.76,32.38 280.04,33.66 IC59.4 | IC59.9 285.12,41.27 283.85,40.01 280.04,40.01 278.76,41.27 IC59.12 278.13,43.18 v275.59,45.72 | IC97.2 434.98,367.67 433.7,367.67 IC97.1 432.44,367.67 388.62,367.67 v386.08,365.12 | v469.26,466.73 581.02,466.73 605.15,490.86 IC139.6 | v460.38,408.31 459.74,408.94 438.15,408.94 436.25,407.04 IC98.2 | v278.13,133.35 288.93,144.15 376.56,144.15 v380.37,147.96
BMR00  (via drill 0.61)
  Top 0.254: v95.89,253.37 95.25,252.73 95.25,215.9 94.61,215.26 M916_7.F1
  Bottom 0.254: v95.89,253.37 268.61,253.37 269.24,254 322.58,254 324.49,252.09 IC76.9
BMR00\  (via drill 0.61)
  Top 0.254: v306.07,249.56 304.8,248.28 v304.8,231.14 | v93.34,236.22 92.08,234.95 92.08,219.07 v92.71,218.44
  Bottom 0.254: v306.07,249.56 306.7,248.92 325.12,248.92 327.02,250.82 IC76.8 | v304.8,231.14 303.53,229.87 139.06,229.87 132.72,236.22 v93.34,236.22 | v92.71,218.44 96.52,218.44 M916_7.H1
BMR01  (via drill 0.61)
  Top 0.254: v80.64,239.4 80.01,238.76 80.01,215.9 80.64,215.26 M916_7.B1
  Bottom 0.254: v80.64,239.4 186.06,239.4 187.32,240.66 321.94,240.66 324.49,243.21 IC76.6
BMR01\  (via drill 0.61)
  Top 0.254: v82.55,220.34 v82.55,238.12
  Bottom 0.254: v82.55,238.12 83.19,238.76 186.69,238.76 187.96,240.03 326.39,240.03 326.39,245.11 325.75,245.75 324.49,245.75 323.21,244.47 IC76.5 | v82.55,220.34 80.64,218.44 78.74,218.44 M916_7.A1
C00  (via drill 0.61)
  Top 0.254: v548,280.67 v548,227.97 v548,194.94 | v322.58,88.27 325.12,85.72 325.12,81.28 IC72.9 | v309.88,191.13 v309.88,88.27 | v54.61,433.7 59.05,429.26 59.05,327.66 59.69,327.02 59.69,306.7 59.05,306.07 59.05,165.74 59.69,165.1 59.69,160.66 70.48,149.86 70.48,94.61 72.39,92.71 IC17.1
  Bottom 0.254: v548,227.97 528.96,208.91 525.14,208.91 523.88,210.19 IC116.10 | v548,280.67 548.64,280.04 596.26,280.04 597.53,281.31 IC133.3 | v322.58,88.27 v309.88,88.27 243.84,88.27 243.21,88.9 152.4,88.9 151.13,90.17 133.35,90.17 132.72,89.53 74.3,89.53 73.03,90.81 IC17.1 | 320.68,189.87 321.94,188.59 IC75.5 | 320.68,189.87 314.32,189.87 313.06,191.13 v309.88,191.13 | v54.61,433.7 52.07,433.7 M916_10.E2 | v548,194.94 544.2,191.13 330.2,191.13 328.93,189.87 320.68,189.87
C00\  (via drill 0.61)
  Top 0.254: v85.09,187.96 85.09,150.5 85.72,149.86 85.72,100.97 85.09,100.33 IC17.9 | v318.77,186.06 318.77,193.04 320.04,194.31 IC75.11 | v309.25,357.5 309.88,356.87 309.88,197.49 308.61,196.22 v308.61,189.87 | v461.64,229.87 461.01,229.24 v461.01,189.87
  Bottom 0.254: v85.09,187.96 85.72,187.32 232.41,187.32 234.31,189.23 264.8,189.23 265.43,189.87 v308.61,189.87 313.06,189.87 314.32,188.59 IC75.2 315.6,187.32 316.87,186.06 v318.77,186.06 323.21,186.06 | 323.21,186.06 324.49,187.32 IC75.6 | v309.25,357.5 311.79,357.5 IC78.1 | v461.64,229.87 476.88,245.11 508,245.11 508.63,245.75 513.72,245.75 514.99,244.47 IC117.2 | v461.01,189.87 457.83,186.69 328.93,186.69 328.3,186.06 323.21,186.06
C01  (via drill 0.61)
  Top 0.254: v76.2,120.65 76.2,93.98 74.93,92.71 IC17.2 | v248.28,125.73 247.65,126.36 247.65,167 248.92,168.28 v248.92,181.61 | v322.58,181.61 325.12,179.07 325.12,176.53 IC74.9 | 270.51,370.2 v271.14,369.57 | 270.51,431.8 v270.51,553.09 | 270.51,431.8 270.51,370.2 | v269.88,431.8 270.51,431.8 | v269.24,182.88 269.24,254 270.51,255.27 270.51,266.06 269.24,267.33 269.24,304.8 271.78,307.34 271.78,316.23 270.51,317.5 270.51,370.2
  Bottom 0.254: v76.2,120.65 200.66,120.65 201.29,120.02 242.57,120.02 v248.28,125.73 | 269.24,181.61 v322.58,181.61 | 269.24,181.61 v248.92,181.61 | v271.14,369.57 274.32,369.57 277.5,366.39 IC65.12 | v270.51,553.09 271.78,554.36 278.76,554.36 280.04,555.62 IC69.11 | v269.88,431.8 240.03,431.8 239.4,431.17 118.75,431.17 117.47,432.44 83.82,432.44 80.64,429.26 56.52,429.26 55.24,430.53 M916_10.F2 | v269.24,182.88 269.24,181.61
C01\  (via drill 0.61)
  Top 0.254: v482.6,279.4 482.6,304.8 | 482.6,304.8 482.6,318.77 IC109.5 | v82.55,106.68 82.55,100.33 IC17.10 | v156.84,116.2 162.56,121.92 v162.56,179.71 | v313.69,180.34 317.5,176.53 IC74.12 | v280.67,387.99 280.67,394.97 IC66.4 | v306.07,382.9 v306.07,304.8 306.07,304.17 307.34,302.89 307.34,198.75 304.17,195.58 v304.17,180.34 | 482.6,304.8 v481.96,304.8
  Bottom 0.254: v482.6,279.4 598.17,279.4 600.08,281.31 IC133.4 | v82.55,106.68 92.08,116.2 v156.84,116.2 | v162.56,179.71 167,184.15 228.6,184.15 232.41,180.34 v304.17,180.34 v313.69,180.34 | IC74.8 327.02,174.62 325.75,173.35 319.4,173.35 318.13,174.62 IC74.12 | v280.67,387.99 285.75,382.9 v306.07,382.9 | v481.96,304.8 v306.07,304.8
CK00  (via drill 0.61)
  Top 0.254: v330.83,267.33 335.92,272.42 v335.92,306.7 | v20.95,309.88 20.95,423.55 21.59,424.18 21.59,440.06 18.41,443.23 v18.41,474.98
  Bottom 0.254: v330.83,267.33 328.3,264.8 324.49,264.8 323.21,266.06 IC77.5 | v335.92,306.7 334.64,307.98 271.14,307.98 270.51,308.61 77.47,308.61 76.2,307.34 61.59,307.34 59.05,309.88 v20.95,309.88 | v18.41,474.98 16.51,476.88 -2.54,476.88 -3.81,478.15 M916_3.P2
CK00\  (via drill 0.61)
